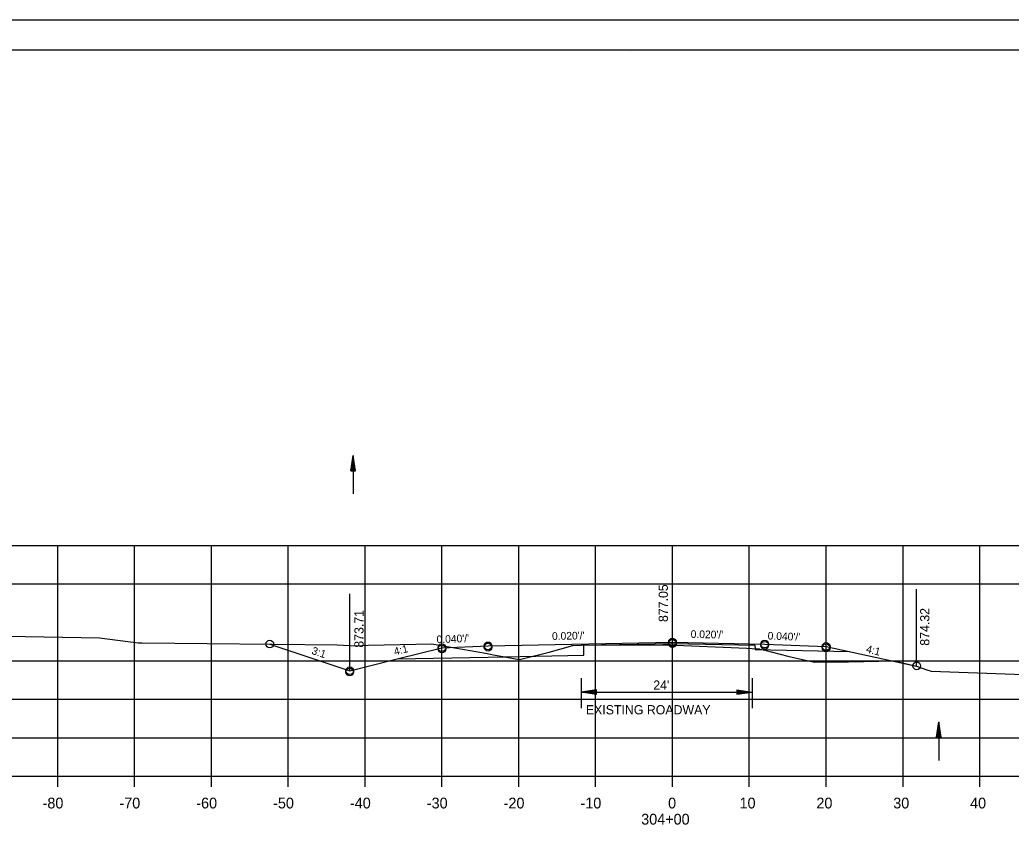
# Model space of a CAD drawing. Extents: x 1486524 to 1499135, y 326561 to 337924.
# Drawn here: x 1488898 to 1489027, y 334165.9 to 334272.7 of the extents above; entities that cross this region are included whole.
import ezdxf

# ---------------------------------------------------------------- set-up
doc = ezdxf.new("R2010")
doc.units = 0
for name, color, linetype in [('E_Const Align', 7, 'Continuous'), ('E_Const Align Station', 7, 'Continuous'), ('E_Ownership Information', 7, 'Continuous'), ('E_Property Line', 7, 'Continuous'), ('E_Proposed ROW and Easements', 7, 'Continuous'), ('E_Proposed ROW Fig Annot', 7, 'Continuous'), ('E_Quarter Calls', 7, 'Continuous'), ('E_Survey Point', 7, 'Continuous'), ('E_Title Sheet', 7, 'Continuous'), ('E_Tract Number', 7, 'Continuous'), ('R_Water Annot', 7, 'Continuous'), ('R_Xsect Elev', 7, 'Continuous'), ('R_Xsect Slope', 7, 'Continuous')]:
    doc.layers.add(name, color=color, linetype=linetype)

msp = doc.modelspace()

# ---------------------------------------------------------------- linework, layer by layer
at = {"layer": 'E_Const Align'}
for p, q in [((1488842.89, 334174.32), (1489122.89, 334174.32)), ((1488902.89, 334172.92), (1488902.89, 334174.32)), ((1488912.89, 334172.92), (1488912.89, 334174.32)), ((1488922.89, 334172.92), (1488922.89, 334174.32)), ((1488932.89, 334172.92), (1488932.89, 334174.32)), ((1488942.89, 334172.92), (1488942.89, 334174.32)), ((1488952.89, 334172.92), (1488952.89, 334174.32)), ((1488962.89, 334172.92), (1488962.89, 334174.32)), ((1488972.89, 334172.92), (1488972.89, 334174.32)), ((1488982.89, 334172.92), (1488982.89, 334174.32)), ((1488992.89, 334172.92), (1488992.89, 334174.32)), ((1489002.89, 334172.92), (1489002.89, 334174.32)), ((1489012.89, 334172.92), (1489012.89, 334174.32)), ((1489022.89, 334172.92), (1489022.89, 334174.32))]:
    msp.add_line(p, q, dxfattribs=at)
at = {"layer": 'E_Ownership Information'}
for p, q in [((1488842.89, 334204.32), (1489122.89, 334204.32)), ((1488902.89, 334174.32), (1488902.89, 334204.32)), ((1488912.89, 334174.32), (1488912.89, 334204.32)), ((1488922.89, 334174.32), (1488922.89, 334204.32)), ((1488932.89, 334174.32), (1488932.89, 334204.32)), ((1488942.89, 334174.32), (1488942.89, 334204.32)), ((1488952.89, 334174.32), (1488952.89, 334204.32)), ((1488962.89, 334174.32), (1488962.89, 334204.32)), ((1488972.89, 334174.32), (1488972.89, 334204.32)), ((1488982.89, 334174.32), (1488982.89, 334204.32)), ((1488992.89, 334174.32), (1488992.89, 334204.32)), ((1489002.89, 334174.32), (1489002.89, 334204.32)), ((1489012.89, 334174.32), (1489012.89, 334204.32)), ((1489022.89, 334174.32), (1489022.89, 334204.32)), ((1488842.89, 334199.32), (1489122.89, 334199.32)), ((1488842.89, 334189.32), (1489122.89, 334189.32)), ((1488842.89, 334184.32), (1489122.89, 334184.32)), ((1488842.89, 334179.32), (1489122.89, 334179.32)), ((1488842.89, 334174.32), (1489122.89, 334174.32))]:
    msp.add_line(p, q, dxfattribs=at)
at = {"layer": 'E_Property Line'}
for p, q in [((1488824.89, 334268.78), (1489141.07, 334268.78)), ((1488977.41, 334268.52), (1488977.41, 334268.52)), ((1488977.41, 334268.52), (1488977.41, 334268.52))]:
    msp.add_line(p, q, dxfattribs=at)
at = {"layer": 'E_Proposed ROW and Easements'}
for p, q in [((1488971, 334187.07), (1488971, 334183.14)), ((1488993.28, 334187.07), (1488993.28, 334183.14)), ((1488973, 334185.55), (1488971, 334185.25)), ((1488973, 334184.95), (1488971, 334185.25)), ((1488973, 334185.5), (1488971.33, 334185.25)), ((1488973, 334185), (1488971.33, 334185.25)), ((1488973, 334185.45), (1488971.68, 334185.25)), ((1488973, 334185.05), (1488971.68, 334185.25)), ((1488973, 334185.4), (1488972.01, 334185.25)), ((1488973, 334185.1), (1488972.01, 334185.25)), ((1488973, 334185.35), (1488972.35, 334185.25)), ((1488973, 334185.15), (1488972.35, 334185.25)), ((1488973, 334185.3), (1488972.68, 334185.25)), ((1488973, 334185.2), (1488972.68, 334185.25)), ((1488973, 334184.95), (1488973, 334185.55)), ((1488991.28, 334185.56), (1488993.28, 334185.26)), ((1488991.28, 334185.56), (1488991.28, 334184.96)), ((1488991.28, 334185.51), (1488992.94, 334185.26)), ((1488991.28, 334185.46), (1488992.6, 334185.26)), ((1488991.28, 334185.41), (1488992.26, 334185.26)), ((1488991.28, 334185.35), (1488991.93, 334185.26)), ((1488991.28, 334185.3), (1488991.59, 334185.26)), ((1488991.28, 334184.96), (1488993.28, 334185.26)), ((1488991.28, 334185.16), (1488991.93, 334185.26)), ((1488991.28, 334185.06), (1488992.6, 334185.26)), ((1488991.28, 334185.01), (1488992.94, 334185.26)), ((1488991.28, 334185.11), (1488992.26, 334185.26)), ((1488991.28, 334185.21), (1488991.59, 334185.26))]:
    msp.add_line(p, q, dxfattribs=at)
at = {"layer": 'E_Proposed ROW Fig Annot'}
for p, q in [((1488941.03, 334214.03), (1488941.33, 334216.03)), ((1488941.63, 334214.03), (1488941.33, 334216.03)), ((1488941.08, 334214.03), (1488941.33, 334215.69)), ((1488941.13, 334214.03), (1488941.33, 334215.35)), ((1488941.18, 334214.03), (1488941.33, 334215.02)), ((1488941.24, 334214.03), (1488941.33, 334214.68)), ((1488941.58, 334214.03), (1488941.33, 334215.69)), ((1488941.53, 334214.03), (1488941.33, 334215.35)), ((1488941.48, 334214.03), (1488941.33, 334215.02)), ((1488941.43, 334214.03), (1488941.33, 334214.68)), ((1488941.03, 334214.03), (1488941.63, 334214.03)), ((1488941.29, 334214.03), (1488941.33, 334214.34)), ((1488941.38, 334214.03), (1488941.33, 334214.34)), ((1488971, 334185.25), (1488993.28, 334185.26)), ((1489017.27, 334179.37), (1489017.57, 334181.37)), ((1489017.32, 334179.37), (1489017.57, 334181.04)), ((1489017.87, 334179.37), (1489017.57, 334181.37)), ((1489017.82, 334179.37), (1489017.57, 334181.04)), ((1489017.37, 334179.37), (1489017.57, 334180.69)), ((1489017.42, 334179.37), (1489017.57, 334180.36)), ((1489017.47, 334179.37), (1489017.57, 334180.02)), ((1489017.52, 334179.37), (1489017.57, 334179.69)), ((1489017.77, 334179.37), (1489017.57, 334180.69)), ((1489017.72, 334179.37), (1489017.57, 334180.36)), ((1489017.67, 334179.37), (1489017.57, 334180.02)), ((1489017.61, 334179.37), (1489017.57, 334179.69)), ((1489017.27, 334179.37), (1489017.87, 334179.37))]:
    msp.add_line(p, q, dxfattribs=at)
at = {"layer": 'E_Quarter Calls'}
msp.add_line((1488812.48, 334272.67), (1489145.82, 334272.67), dxfattribs=at)
for points in [[(1488812.48, 334272.67), (1489145.82, 334272.67), (1489145.82, 334059.33), (1488812.48, 334059.33)], [(1489058.81, 334268.78), (1489058.81, 334258.9), (1489094.54, 334258.9), (1489094.54, 334255.98), (1489117.74, 334255.98), (1489117.74, 334231.64), (1489141.07, 334231.64), (1489141.07, 334063.32), (1488824.89, 334063.32), (1488824.89, 334268.78)]]:
    msp.add_lwpolyline(points, close=True, dxfattribs=at)
for centre in [(1488930.49, 334191.49), (1488930.49, 334191.49), (1488952.89, 334191.02), (1488952.89, 334191.02), (1488952.89, 334190.85), (1488958.89, 334191.26), (1488958.89, 334191.26), (1488958.89, 334191.09), (1488982.89, 334191.74), (1488982.89, 334191.74), (1488982.89, 334191.57), (1488994.89, 334191.5), (1488994.89, 334191.5), (1488994.89, 334191.33), (1489002.89, 334191.18), (1489002.89, 334191.18), (1489002.89, 334191.01), (1489014.68, 334188.66), (1488940.89, 334188.02), (1488940.89, 334188.02), (1488940.89, 334187.85)]:
    msp.add_circle(centre, 0.5, dxfattribs=at)
at = {"layer": 'E_Survey Point'}
msp.add_lwpolyline([(1488947.06, 334189.57), (1488958.89, 334189.8), (1488971.36, 334190.06), (1488971.36, 334191.35), (1488982.89, 334191.58), (1488993.62, 334191.36), (1488993.63, 334190.78), (1489005.94, 334190.53)], dxfattribs=at)
at = {"layer": 'E_Title Sheet'}
msp.add_lwpolyline([(1488930.49, 334191.49), (1488940.89, 334188.02), (1488947.06, 334189.57), (1488952.89, 334191.02), (1488958.89, 334191.26), (1488982.89, 334191.74), (1488994.89, 334191.5), (1489002.89, 334191.18), (1489014.63, 334188.64)], dxfattribs=at)
at = {"layer": 'E_Tract Number'}
msp.add_lwpolyline([(1488896.3, 334192.54), (1488908.34, 334192.29), (1488913.36, 334191.65), (1488913.86, 334191.65), (1488939.26, 334191.4), (1488941.74, 334191.28), (1488943.3, 334191.35), (1488951.58, 334191.51), (1488958.55, 334190.29), (1488959.19, 334190.18), (1488959.38, 334190.15), (1488962.93, 334189.48), (1488963.14, 334189.52), (1488966.85, 334190.42), (1488969.64, 334191.23), (1488969.85, 334191.29), (1488969.92, 334191.29), (1488970.99, 334191.34), (1488981.63, 334191.39), (1488982.27, 334191.39), (1488992.55, 334190.96), (1488993.25, 334190.93), (1488994.19, 334190.86), (1488994.25, 334190.85), (1488994.9, 334190.69), (1488997.9, 334189.92), (1489000.19, 334189.4), (1489001.43, 334189.13), (1489004.05, 334189.18), (1489004.53, 334189.18), (1489005.79, 334189.2), (1489011.76, 334189.3), (1489012.99, 334189), (1489014.63, 334188.64), (1489015.98, 334188.14), (1489016.54, 334187.97), (1489038.23, 334187.2)], dxfattribs=at)
at = {"layer": 'R_Water Annot'}
for p, q in [((1488941.33, 334216.03), (1488941.33, 334211.03)), ((1489017.57, 334181.37), (1489017.57, 334176.37))]:
    msp.add_line(p, q, dxfattribs=at)
at = {"layer": 'R_Xsect Elev'}
for p, q in [((1488982.89, 334191.36), (1488982.89, 334201.36)), ((1488940.89, 334188.02), (1488940.89, 334198.02)), ((1489014.63, 334188.64), (1489014.63, 334198.64))]:
    msp.add_line(p, q, dxfattribs=at)

# ---------------------------------------------------------------- texts
at = {"layer": 'E_Const Align Station'}
for s, p in [('-80', (1488900.92, 334170.12)), ('-70', (1488910.92, 334170.12)), ('-60', (1488920.92, 334170.12)), ('-50', (1488930.92, 334170.12)), ('-40', (1488940.92, 334170.12)), ('-30', (1488950.92, 334170.12)), ('-20', (1488960.92, 334170.12)), ('-10', (1488970.92, 334170.12)), ('0', (1488982.32, 334170.12)), ('10', (1488991.62, 334170.12)), ('20', (1489001.62, 334170.12)), ('30', (1489011.62, 334170.12)), ('40', (1489021.62, 334170.12)), ('304+00', (1488978.82, 334168.02))]:
    msp.add_text(s, height=1.4, dxfattribs=at).set_placement(p)
at = {"layer": 'E_Proposed ROW Fig Annot'}
for s, p in [("24'", (1488980.39, 334185.56)), ('EXISTING ROADWAY', (1488971.62, 334182.35))]:
    msp.add_text(s, height=1.2, dxfattribs=at).set_placement(p)
at = {"layer": 'R_Xsect Elev'}
for s, p in [('877.05', (1488982.29, 334194.36)), ('873.71', (1488942.69, 334191.02)), ('874.32', (1489016.32, 334191.28))]:
    msp.add_text(s, height=1.2, rotation=90, dxfattribs=at).set_placement(p)
at = {"layer": 'R_Xsect Slope'}
for s, rotation, p in [("0.040'/'", 2.2906, (1488952.21, 334191.6)), ("0.020'/'", 1.1458, (1488967.22, 334192.03)), ("0.020'/'", 358.8542, (1488985.25, 334192.3)), ("0.040'/'", 357.7094, (1488995.26, 334192.09)), ('4:1', 14.0362, (1488946.76, 334190.01)), ('4:1', 345.9638, (1489008.01, 334190.42)), ('3:1', 341.5651, (1488935.85, 334190.23))]:
    msp.add_text(s, height=1, rotation=rotation, dxfattribs=at).set_placement(p)

doc.saveas('drawing.dxf')
